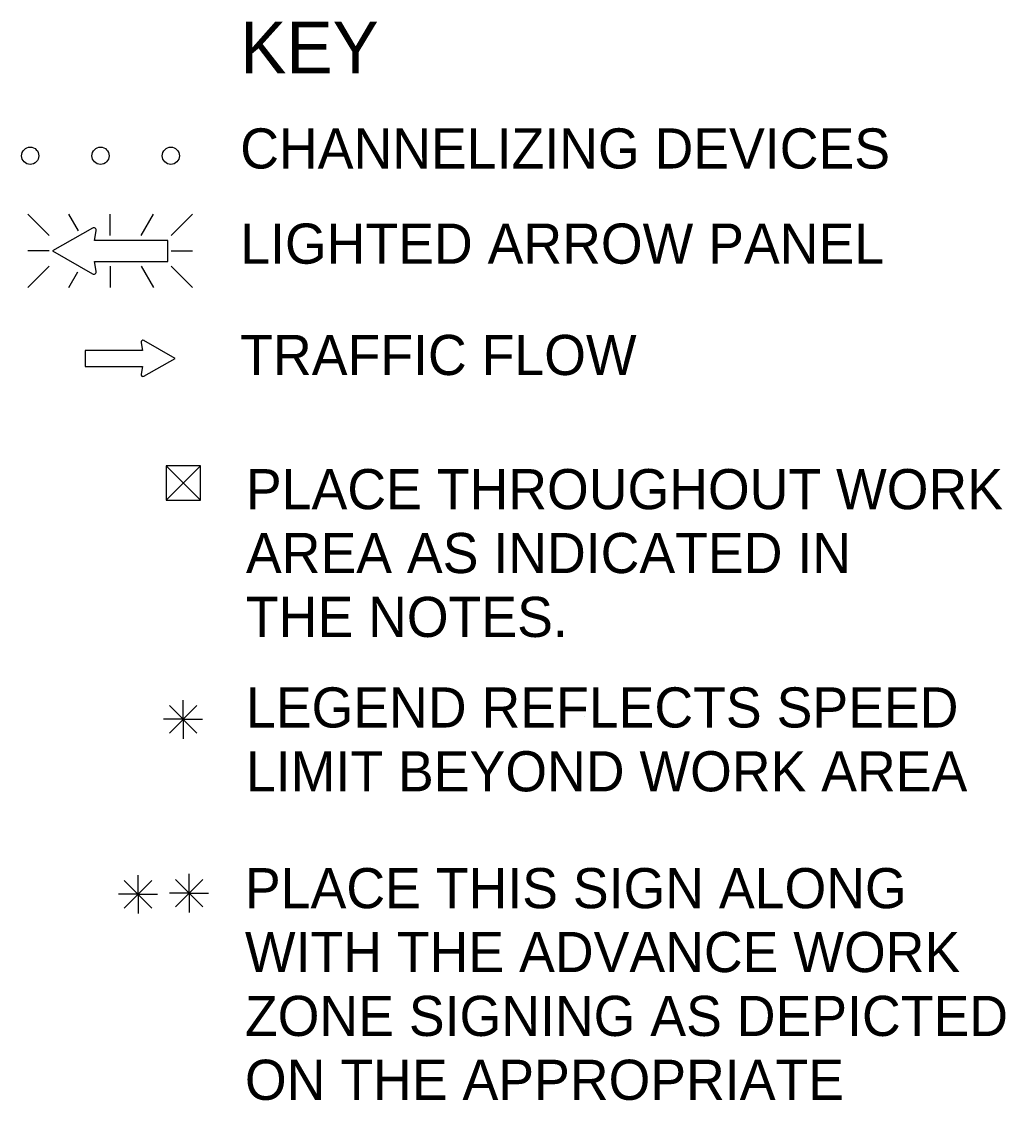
# Model space of a CAD drawing. Extents: x 16553 to 18478, y 5759 to 7026.
# Drawn here: x 17180.9 to 17409, y 6674.4 to 6924.4 of the extents above; entities that cross this region are included whole.
import ezdxf

# ---------------------------------------------------------------- set-up
doc = ezdxf.new("R2010")
doc.units = 0
for name, color, linetype in [('MT_SCRATCH_LEVEL_E', 7, 'Continuous'), ('TRAFFIC_SIGNS_PR', 7, 'Continuous'), ('TYPICAL_TEXT_DIMEN_EX', 7, 'Continuous'), ('TYPICAL_TEXT_DIMEN_PR', 7, 'Continuous')]:
    doc.layers.add(name, color=color, linetype=linetype)

msp = doc.modelspace()

# ---------------------------------------------------------------- linework, layer by layer
at = {"layer": 'MT_SCRATCH_LEVEL_E'}
for p, q in [((17208.65, 6849.99), (17208.96, 6848.21)), ((17216.57, 6846.36), (17209.33, 6850.47)), ((17208.96, 6848.21), (17195.71, 6848.21)), ((17195.71, 6848.21), (17195.71, 6844.47)), ((17195.71, 6844.47), (17208.96, 6844.47)), ((17208.96, 6844.47), (17208.65, 6842.69)), ((17209.33, 6842.22), (17216.57, 6846.36))]:
    msp.add_line(p, q, dxfattribs=at)
for centre, start, end in [((17209.11, 6850.07), 60.4248, 189.9638), ((17209.11, 6842.62), 170.0362, 299.7731)]:
    msp.add_arc(centre, 0.463, start, end, dxfattribs=at)
at = {"layer": 'TRAFFIC_SIGNS_PR'}
for p, q in [((17182.39, 6879.74), (17187.32, 6874.81)), ((17194.15, 6875.92), (17191.94, 6879.75)), ((17201.47, 6874.81), (17201.47, 6879.75)), ((17208.7, 6874.81), (17211.55, 6879.75)), ((17215.62, 6874.81), (17220.55, 6879.75)), ((17187.32, 6871.26), (17182.39, 6871.26)), ((17215.62, 6871.26), (17220.55, 6871.26)), ((17182.39, 6862.77), (17187.32, 6867.7)), ((17201.47, 6867.7), (17201.47, 6862.77)), ((17211.6, 6862.77), (17208.75, 6867.7)), ((17215.62, 6867.7), (17220.55, 6862.76)), ((17191.9, 6862.77), (17194.01, 6866.43))]:
    msp.add_line(p, q, dxfattribs=at)
for points in [[(17197.4, 6876.53), (17188.1, 6871.26), (17197.4, 6865.94)], [(17198.27, 6866.56), (17197.87, 6868.83), (17214.88, 6868.83), (17214.88, 6873.63), (17197.87, 6873.63), (17198.27, 6875.91)]]:
    msp.add_lwpolyline(points, dxfattribs=at)
for centre in [(17182.95, 6893.29), (17199.25, 6893.29), (17215.55, 6893.29)]:
    msp.add_circle(centre, 2, dxfattribs=at)
for centre, radius, start, end in [((17197.68, 6876.01), 0.598, 350.7308, 118.8916), ((17197.68, 6866.46), 0.597, 241.4833, 9.9593)]:
    msp.add_arc(centre, radius, start, end, dxfattribs=at)
at = {"layer": 'TYPICAL_TEXT_DIMEN_PR'}
for p, q in [((17214.46, 6821.48), (17222.46, 6813.48)), ((17214.46, 6813.48), (17222.46, 6821.48)), ((17218.42, 6762.73), (17218.42, 6767.18)), ((17221.61, 6765.91), (17215.23, 6759.54)), ((17215.24, 6765.91), (17221.61, 6759.54)), ((17218.42, 6762.73), (17213.89, 6762.73)), ((17218.42, 6762.73), (17221.61, 6762.73)), ((17218.42, 6762.73), (17222.9, 6762.73)), ((17218.42, 6762.73), (17218.42, 6758.23)), ((17219.79, 6722.45), (17219.79, 6726.91)), ((17204.77, 6725.37), (17211.14, 6719)), ((17211.14, 6725.37), (17204.77, 6719)), ((17207.95, 6722.19), (17207.95, 6726.64)), ((17216.6, 6725.64), (17222.98, 6719.26)), ((17222.98, 6725.64), (17216.6, 6719.26)), ((17207.95, 6722.19), (17203.42, 6722.19)), ((17207.95, 6722.19), (17211.14, 6722.19)), ((17207.95, 6722.19), (17212.43, 6722.19)), ((17207.95, 6722.19), (17207.95, 6717.69)), ((17219.79, 6722.45), (17215.26, 6722.45)), ((17219.79, 6722.45), (17222.98, 6722.45)), ((17219.79, 6722.45), (17224.27, 6722.45)), ((17219.79, 6722.45), (17219.79, 6717.95))]:
    msp.add_line(p, q, dxfattribs=at)
msp.add_lwpolyline([(17214.46, 6821.48), (17214.46, 6813.48), (17222.46, 6813.48), (17222.46, 6821.48)], close=True, dxfattribs=at)
msp.add_open_spline([(17311.37, 6763.31), (17311.39, 6763.31), (17311.4, 6763.31), (17311.4, 6763.31)], degree=2, dxfattribs=at)

# ---------------------------------------------------------------- texts
at = {"layer": 'TYPICAL_TEXT_DIMEN_EX'}
for s, height, p in [('KEY', 12, (17231.64, 6912.39)), ('CHANNELIZING DEVICES', 9.3, (17231.64, 6890.34)), ('LIGHTED ARROW PANEL', 9.3, (17231.64, 6868.29)), ('TRAFFIC FLOW', 9.3, (17231.64, 6842.49)), ('PLACE THROUGHOUT WORK', 9.3, (17232.96, 6811.4)), ('AREA AS INDICATED IN', 9.3, (17232.96, 6796.6)), ('THE NOTES.', 9.3, (17232.96, 6781.8)), ('LEGEND REFLECTS SPEED', 9.3, (17232.97, 6760.82)), ('LIMIT BEYOND WORK AREA', 9.3, (17232.97, 6746.03)), ('PLACE THIS SIGN ALONG', 9.3, (17232.73, 6718.95)), ('WITH THE ADVANCE WORK', 9.3, (17232.73, 6704.15)), ('ZONE SIGNING AS DEPICTED', 9.3, (17232.73, 6689.35)), ('ON THE APPROPRIATE', 9.3, (17232.73, 6674.55))]:
    msp.add_text(s, height=height, dxfattribs=at).set_placement(p)

doc.saveas('drawing.dxf')
